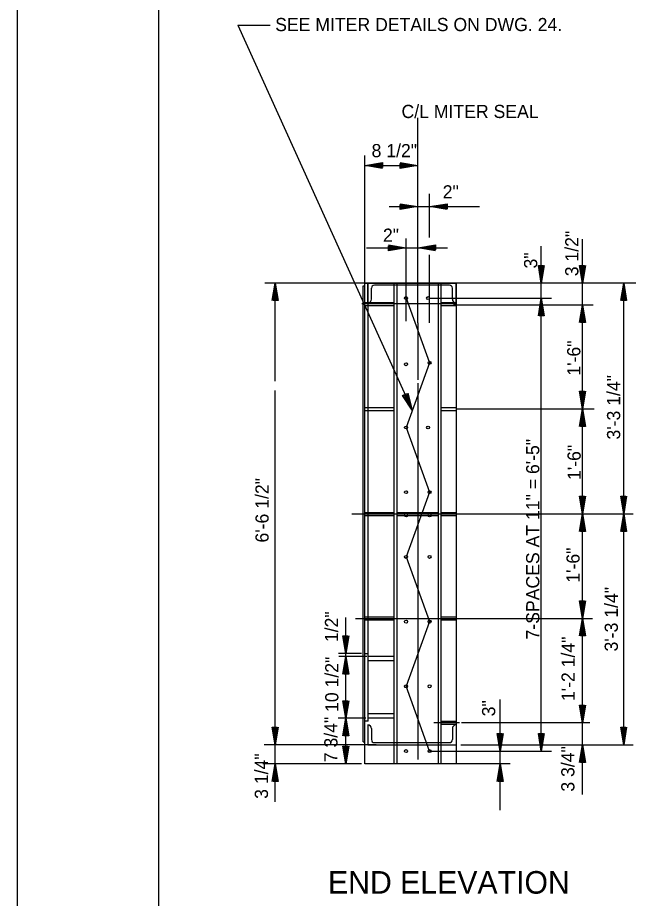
# Model space of a CAD drawing. Extents: x 0.6 to 54, y 0.6 to 38.
# Drawn here: x 0.63 to 9.53, y 12.03 to 24.51 of the extents above; entities that cross this region are included whole.
import ezdxf

# ---------------------------------------------------------------- set-up
doc = ezdxf.new("R2010")
doc.units = 0
for name, color, linetype in [('Level 1', 7, 'Continuous'), ('Level 2', 7, 'Continuous'), ('Level 25', 7, 'Continuous'), ('Level 50', 7, 'Continuous')]:
    doc.layers.add(name, color=color, linetype=linetype)

msp = doc.modelspace()

# ---------------------------------------------------------------- linework, layer by layer
at = {"layer": 'Level 1'}
for points in [[(0.625, 37.958), (53.958, 37.958), (53.958, 0.625), (0.625, 0.625)], [(2.625, 37.292), (53.292, 37.292), (53.292, 1.292), (2.625, 1.292)]]:
    msp.add_lwpolyline(points, close=True, dxfattribs=at)
at = {"layer": 'Level 25'}
for p, q in [((3.742, 24.398), (4.204, 24.398)), ((6.293, 20.185), (6.293, 23.087)), ((5.543, 20.747), (5.543, 22.555)), ((5.543, 22.412), (6.293, 22.412)), ((6.459, 21.394), (6.459, 22.008)), ((5.888, 21.829), (6.293, 21.829)), ((6.293, 21.829), (6.459, 21.829)), ((6.459, 21.829), (7.166, 21.829)), ((6.126, 20.206), (6.126, 21.379)), ((8.626, 20.747), (8.626, 21.366)), ((5.564, 21.245), (6.126, 21.245)), ((6.126, 21.245), (6.293, 21.245)), ((6.293, 21.245), (6.712, 21.245)), ((8.042, 20.747), (8.042, 21.271)), ((6.459, 20.185), (6.459, 21.147)), ((5.591, 20.747), (4.128, 20.747)), ((4.273, 19.355), (4.273, 20.747)), ((5.543, 20.747), (6.834, 20.747)), ((5.543, 19.247), (5.543, 20.747)), ((5.584, 20.466), (5.584, 20.747)), ((5.591, 19.247), (5.591, 20.747)), ((5.959, 19.247), (5.959, 20.747)), ((6.001, 19.247), (6.001, 20.747)), ((6.584, 19.247), (6.584, 20.747)), ((6.626, 19.247), (6.626, 20.747)), ((9.38, 20.747), (6.834, 20.747)), ((6.834, 20.747), (6.834, 19.247)), ((6.834, 20.466), (6.834, 20.747)), ((8.042, 20.534), (8.042, 20.747)), ((8.626, 20.435), (8.626, 20.747)), ((9.209, 17.477), (9.209, 20.747)), ((5.517, 20.706), (5.543, 20.706)), ((5.517, 19.247), (5.517, 20.706)), ((5.636, 20.518), (5.636, 20.675)), ((6.782, 20.518), (6.782, 20.675)), ((5.543, 20.471), (5.959, 20.471)), ((6.126, 20.534), (6.459, 19.617)), ((6.459, 20.534), (8.186, 20.534)), ((6.626, 20.471), (6.834, 20.471)), ((8.042, 14.117), (8.042, 20.534)), ((6.834, 20.451), (5.5, 20.451)), ((5.543, 20.43), (5.959, 20.43)), ((6.626, 20.43), (6.834, 20.43)), ((7.023, 20.435), (6.799, 20.435)), ((8.778, 20.435), (7.023, 20.435)), ((8.626, 18.964), (8.626, 20.435)), ((6.293, 20.185), (6.293, 19.374)), ((6.459, 19.617), (6.126, 18.7)), ((4.273, 13.935), (4.273, 19.225)), ((5.517, 14.248), (5.517, 19.247)), ((5.543, 14.248), (5.543, 19.247)), ((5.591, 15.497), (5.591, 19.247)), ((5.959, 13.935), (5.959, 19.247)), ((6.001, 13.935), (6.001, 19.247)), ((6.293, 19.326), (6.293, 13.996)), ((6.584, 13.935), (6.584, 19.247)), ((6.626, 13.935), (6.626, 19.247)), ((6.834, 19.247), (6.834, 13.935)), ((5.543, 18.984), (5.959, 18.984)), ((6.626, 18.984), (6.834, 18.984)), ((5.543, 18.943), (5.959, 18.943)), ((6.626, 18.943), (6.834, 18.943)), ((6.834, 18.964), (8.791, 18.964)), ((8.626, 17.477), (8.626, 18.964)), ((6.126, 18.7), (6.459, 17.784)), ((6.459, 17.784), (6.126, 16.867)), ((5.36, 17.477), (6.834, 17.477)), ((5.543, 17.497), (5.959, 17.497)), ((6.001, 17.497), (6.584, 17.497)), ((6.626, 17.497), (6.834, 17.497)), ((8.626, 15.997), (8.626, 17.477)), ((9.209, 14.206), (9.209, 17.477)), ((5.543, 17.456), (5.959, 17.456)), ((6.001, 17.456), (6.584, 17.456)), ((6.626, 17.456), (6.834, 17.456)), ((6.126, 16.867), (6.459, 15.95)), ((5.273, 15.497), (5.273, 16.01)), ((5.41, 15.997), (6.887, 15.997)), ((5.543, 16.018), (5.959, 16.018)), ((5.543, 15.977), (5.959, 15.977)), ((6.626, 16.018), (6.834, 16.018)), ((6.626, 15.977), (6.834, 15.977)), ((6.834, 15.997), (8.767, 15.997)), ((8.626, 14.518), (8.626, 15.997)), ((6.459, 15.95), (6.126, 15.034)), ((5.494, 15.497), (5.17, 15.497)), ((5.273, 15.417), (5.273, 15.528)), ((5.543, 15.497), (5.591, 15.497)), ((5.591, 14.539), (5.591, 15.497)), ((5.571, 15.456), (5.173, 15.456)), ((5.273, 14.581), (5.273, 15.456)), ((5.959, 15.456), (5.591, 15.456)), ((5.959, 15.393), (5.591, 15.393)), ((7.459, 14.117), (7.459, 14.848)), ((5.959, 14.643), (5.591, 14.643)), ((5.559, 14.581), (5.164, 14.581)), ((5.273, 13.935), (5.273, 14.581)), ((5.591, 14.539), (5.543, 14.539)), ((5.584, 14.487), (5.584, 14.206)), ((5.959, 14.581), (5.591, 14.581)), ((6.884, 14.518), (6.52, 14.518)), ((6.626, 14.539), (6.834, 14.539)), ((6.626, 14.497), (6.834, 14.497)), ((6.834, 14.487), (6.834, 14.206)), ((8.731, 14.518), (6.91, 14.518)), ((8.626, 14.206), (8.626, 14.518)), ((5.636, 14.435), (5.636, 14.279)), ((6.782, 14.435), (6.782, 14.279)), ((5.517, 14.248), (5.543, 14.248)), ((5.543, 13.935), (5.543, 14.248)), ((5.703, 14.206), (4.119, 14.206)), ((6.459, 14.117), (8.186, 14.117)), ((6.586, 14.206), (6.834, 14.206)), ((6.9, 14.206), (9.345, 14.206)), ((7.459, 13.935), (7.459, 14.117)), ((8.626, 13.5), (8.626, 14.206)), ((5.494, 13.935), (4.099, 13.935)), ((4.273, 13.399), (4.273, 13.935)), ((6.834, 13.935), (5.543, 13.935)), ((7.599, 13.935), (6.834, 13.935)), ((7.459, 13.279), (7.459, 13.935))]:
    msp.add_line(p, q, dxfattribs=at)
for centre in [(6.126, 20.534), (6.439, 20.534), (6.126, 19.596), (6.459, 19.617), (6.126, 18.7), (6.439, 18.7), (6.126, 17.784), (6.459, 17.784), (6.126, 17.456), (6.459, 17.456), (6.126, 16.867), (6.459, 16.867), (6.126, 15.95), (6.459, 15.95), (6.126, 15.034), (6.459, 15.034), (6.126, 14.117), (6.459, 14.117)]:
    msp.add_circle(centre, 0.0208, dxfattribs=at)
at = {"layer": 'Level 50'}
for p, q in [((3.742, 24.398), (6.215, 18.945)), ((5.543, 22.412), (5.543, 22.412)), ((5.612, 22.412), (5.612, 22.412)), ((6.223, 22.412), (6.223, 22.412)), ((6.293, 22.412), (6.293, 22.412)), ((6.223, 21.829), (6.223, 21.829)), ((6.293, 21.829), (6.293, 21.829)), ((6.459, 21.829), (6.459, 21.829)), ((6.529, 21.829), (6.529, 21.829)), ((6.057, 21.245), (6.057, 21.245)), ((6.057, 21.245), (6.057, 21.245)), ((6.126, 21.245), (6.126, 21.245)), ((6.126, 21.245), (6.126, 21.245)), ((6.293, 21.245), (6.293, 21.245)), ((6.362, 21.245), (6.362, 21.245)), ((4.273, 20.747), (4.273, 20.747)), ((6.834, 20.747), (5.584, 20.747)), ((6.741, 20.716), (5.678, 20.716)), ((8.042, 20.817), (8.042, 20.817)), ((8.042, 20.747), (8.042, 20.747)), ((8.626, 20.817), (8.626, 20.817)), ((8.626, 20.747), (8.626, 20.747)), ((9.209, 20.747), (9.209, 20.747)), ((4.273, 20.678), (4.273, 20.678)), ((9.209, 20.678), (9.209, 20.678)), ((8.042, 20.534), (8.042, 20.534)), ((8.042, 20.464), (8.042, 20.464)), ((8.626, 20.435), (8.626, 20.435)), ((8.626, 20.366), (8.626, 20.366)), ((6.186, 19.008), (6.186, 19.008)), ((8.626, 19.033), (8.626, 19.033)), ((6.215, 18.945), (6.215, 18.945)), ((8.626, 18.964), (8.626, 18.964)), ((8.626, 18.964), (8.626, 18.964)), ((8.626, 18.894), (8.626, 18.894)), ((6.834, 17.477), (9.344, 17.477)), ((8.626, 17.546), (8.626, 17.546)), ((8.626, 17.477), (8.626, 17.477)), ((8.626, 17.477), (8.626, 17.477)), ((9.209, 17.546), (9.209, 17.546)), ((9.209, 17.477), (9.209, 17.477)), ((9.209, 17.477), (9.209, 17.477)), ((8.626, 17.407), (8.626, 17.407)), ((9.209, 17.407), (9.209, 17.407)), ((8.626, 16.067), (8.626, 16.067)), ((8.626, 15.997), (8.626, 15.997)), ((8.626, 15.997), (8.626, 15.997)), ((8.626, 15.928), (8.626, 15.928)), ((5.273, 15.567), (5.273, 15.567)), ((5.273, 15.497), (5.273, 15.497)), ((5.273, 15.456), (5.273, 15.456)), ((5.273, 15.456), (5.273, 15.456)), ((5.273, 15.386), (5.273, 15.386)), ((5.273, 15.386), (5.273, 15.386)), ((6.459, 14.117), (6.126, 15.034)), ((5.273, 14.65), (5.273, 14.65)), ((5.273, 14.581), (5.273, 14.581)), ((5.273, 14.581), (5.273, 14.581)), ((5.273, 14.511), (5.273, 14.511)), ((8.626, 14.588), (8.626, 14.588)), ((8.626, 14.518), (8.626, 14.518)), ((4.273, 14.275), (4.273, 14.275)), ((5.678, 14.237), (6.741, 14.237)), ((9.209, 14.275), (9.209, 14.275)), ((4.273, 14.206), (4.273, 14.206)), ((5.584, 14.206), (6.834, 14.206)), ((7.459, 14.186), (7.459, 14.186)), ((7.459, 14.117), (7.459, 14.117)), ((8.042, 14.186), (8.042, 14.186)), ((8.042, 14.117), (8.042, 14.117)), ((8.626, 14.206), (8.626, 14.206)), ((8.626, 14.137), (8.626, 14.137)), ((9.209, 14.206), (9.209, 14.206)), ((5.273, 14.004), (5.273, 14.004)), ((4.273, 13.935), (4.273, 13.935)), ((4.273, 13.866), (4.273, 13.866)), ((5.273, 13.935), (5.273, 13.935)), ((7.459, 13.935), (7.459, 13.935)), ((7.459, 13.866), (7.459, 13.866))]:
    msp.add_line(p, q, dxfattribs=at)
for points in [[(5.792, 22.371), (5.543, 22.412), (5.792, 22.453), (5.792, 22.383), (5.612, 22.412), (5.782, 22.44), (5.782, 22.395), (5.679, 22.412), (5.771, 22.427), (5.771, 22.408), (5.748, 22.412)], [(6.043, 22.453), (6.293, 22.412), (6.043, 22.371), (6.043, 22.441), (6.223, 22.412), (6.054, 22.384), (6.054, 22.429), (6.157, 22.412), (6.065, 22.397), (6.065, 22.416), (6.087, 22.412)], [(6.043, 21.87), (6.293, 21.829), (6.043, 21.787), (6.043, 21.858), (6.223, 21.829), (6.054, 21.801), (6.054, 21.846), (6.157, 21.829), (6.065, 21.814), (6.065, 21.833), (6.087, 21.829)], [(6.709, 21.787), (6.459, 21.829), (6.709, 21.87), (6.709, 21.799), (6.529, 21.829), (6.698, 21.857), (6.698, 21.811), (6.595, 21.829), (6.687, 21.843), (6.687, 21.825), (6.665, 21.829)], [(5.877, 21.287), (6.126, 21.245), (5.877, 21.204), (5.877, 21.275), (6.057, 21.245), (5.887, 21.217), (5.887, 21.263), (5.99, 21.245), (5.898, 21.231), (5.898, 21.249), (5.921, 21.245)], [(5.877, 21.287), (6.126, 21.245), (5.877, 21.204), (5.877, 21.275), (6.057, 21.245), (5.887, 21.217), (5.887, 21.263), (5.99, 21.245), (5.898, 21.231), (5.898, 21.249), (5.921, 21.245)], [(6.542, 21.204), (6.293, 21.245), (6.542, 21.287), (6.542, 21.216), (6.362, 21.245), (6.531, 21.273), (6.531, 21.228), (6.429, 21.245), (6.521, 21.26), (6.521, 21.241), (6.498, 21.245)], [(8.084, 20.997), (8.042, 20.747), (8.001, 20.997), (8.072, 20.997), (8.042, 20.817), (8.014, 20.986), (8.06, 20.986), (8.042, 20.883), (8.028, 20.975), (8.046, 20.975), (8.042, 20.953)], [(8.667, 20.997), (8.626, 20.747), (8.584, 20.997), (8.655, 20.997), (8.626, 20.817), (8.598, 20.986), (8.643, 20.986), (8.626, 20.883), (8.611, 20.975), (8.63, 20.975), (8.626, 20.953)], [(4.232, 20.498), (4.273, 20.747), (4.315, 20.498), (4.244, 20.498), (4.273, 20.678), (4.301, 20.509), (4.256, 20.509), (4.273, 20.611), (4.288, 20.519), (4.269, 20.519), (4.273, 20.542)], [(9.168, 20.498), (9.209, 20.747), (9.25, 20.498), (9.18, 20.498), (9.209, 20.678), (9.237, 20.509), (9.192, 20.509), (9.209, 20.611), (9.224, 20.519), (9.205, 20.519), (9.209, 20.542)], [(8.001, 20.284), (8.042, 20.534), (8.084, 20.284), (8.013, 20.284), (8.042, 20.464), (8.07, 20.295), (8.025, 20.295), (8.042, 20.398), (8.057, 20.306), (8.038, 20.306), (8.042, 20.328)], [(8.584, 20.186), (8.626, 20.435), (8.667, 20.186), (8.596, 20.186), (8.626, 20.366), (8.654, 20.197), (8.608, 20.197), (8.626, 20.299), (8.64, 20.207), (8.622, 20.207), (8.626, 20.23)], [(6.15, 19.189), (6.215, 18.945), (6.074, 19.155), (6.139, 19.184), (6.186, 19.008), (6.091, 19.151), (6.132, 19.169), (6.159, 19.069), (6.107, 19.146), (6.124, 19.154), (6.13, 19.132)], [(8.667, 19.213), (8.626, 18.964), (8.584, 19.213), (8.655, 19.213), (8.626, 19.033), (8.598, 19.202), (8.643, 19.202), (8.626, 19.1), (8.611, 19.192), (8.63, 19.192), (8.626, 19.169)], [(8.584, 18.714), (8.626, 18.964), (8.667, 18.714), (8.596, 18.714), (8.626, 18.894), (8.654, 18.725), (8.608, 18.725), (8.626, 18.828), (8.64, 18.736), (8.622, 18.736), (8.626, 18.758)], [(8.667, 17.726), (8.626, 17.477), (8.584, 17.726), (8.655, 17.726), (8.626, 17.546), (8.598, 17.715), (8.643, 17.715), (8.626, 17.613), (8.611, 17.705), (8.63, 17.705), (8.626, 17.682)], [(9.25, 17.726), (9.209, 17.477), (9.168, 17.726), (9.238, 17.726), (9.209, 17.546), (9.181, 17.715), (9.226, 17.715), (9.209, 17.613), (9.194, 17.705), (9.213, 17.705), (9.209, 17.682)], [(8.584, 17.227), (8.626, 17.477), (8.667, 17.227), (8.596, 17.227), (8.626, 17.407), (8.654, 17.238), (8.608, 17.238), (8.626, 17.341), (8.64, 17.249), (8.622, 17.249), (8.626, 17.271)], [(9.168, 17.227), (9.209, 17.477), (9.25, 17.227), (9.18, 17.227), (9.209, 17.407), (9.237, 17.238), (9.192, 17.238), (9.209, 17.341), (9.224, 17.249), (9.205, 17.249), (9.209, 17.271)], [(8.667, 16.247), (8.626, 15.997), (8.584, 16.247), (8.655, 16.247), (8.626, 16.067), (8.598, 16.236), (8.643, 16.236), (8.626, 16.133), (8.611, 16.225), (8.63, 16.225), (8.626, 16.203)], [(8.584, 15.748), (8.626, 15.997), (8.667, 15.748), (8.596, 15.748), (8.626, 15.928), (8.654, 15.759), (8.608, 15.759), (8.626, 15.861), (8.64, 15.769), (8.622, 15.769), (8.626, 15.792)], [(5.315, 15.747), (5.273, 15.497), (5.232, 15.747), (5.303, 15.747), (5.273, 15.567), (5.245, 15.736), (5.291, 15.736), (5.273, 15.633), (5.259, 15.725), (5.277, 15.725), (5.273, 15.703)], [(5.232, 15.206), (5.273, 15.456), (5.315, 15.206), (5.244, 15.206), (5.273, 15.386), (5.301, 15.217), (5.256, 15.217), (5.273, 15.32), (5.288, 15.228), (5.269, 15.228), (5.273, 15.25)], [(5.232, 15.206), (5.273, 15.456), (5.315, 15.206), (5.244, 15.206), (5.273, 15.386), (5.301, 15.217), (5.256, 15.217), (5.273, 15.32), (5.288, 15.228), (5.269, 15.228), (5.273, 15.25)], [(5.315, 14.83), (5.273, 14.581), (5.232, 14.83), (5.303, 14.83), (5.273, 14.65), (5.245, 14.819), (5.291, 14.819), (5.273, 14.717), (5.259, 14.809), (5.277, 14.809), (5.273, 14.786)], [(8.667, 14.768), (8.626, 14.518), (8.584, 14.768), (8.655, 14.768), (8.626, 14.588), (8.598, 14.757), (8.643, 14.757), (8.626, 14.654), (8.611, 14.746), (8.63, 14.746), (8.626, 14.724)], [(5.232, 14.331), (5.273, 14.581), (5.315, 14.331), (5.244, 14.331), (5.273, 14.511), (5.301, 14.342), (5.256, 14.342), (5.273, 14.445), (5.288, 14.353), (5.269, 14.353), (5.273, 14.375)], [(4.315, 14.455), (4.273, 14.206), (4.232, 14.455), (4.303, 14.455), (4.273, 14.275), (4.245, 14.445), (4.291, 14.445), (4.273, 14.342), (4.259, 14.434), (4.277, 14.434), (4.273, 14.411)], [(7.5, 14.366), (7.459, 14.117), (7.418, 14.366), (7.488, 14.366), (7.459, 14.186), (7.431, 14.356), (7.476, 14.356), (7.459, 14.253), (7.444, 14.345), (7.463, 14.345), (7.459, 14.322)], [(8.084, 14.366), (8.042, 14.117), (8.001, 14.366), (8.072, 14.366), (8.042, 14.186), (8.014, 14.356), (8.06, 14.356), (8.042, 14.253), (8.028, 14.345), (8.046, 14.345), (8.042, 14.322)], [(9.25, 14.455), (9.209, 14.206), (9.168, 14.455), (9.238, 14.455), (9.209, 14.275), (9.181, 14.445), (9.226, 14.445), (9.209, 14.342), (9.194, 14.434), (9.213, 14.434), (9.209, 14.411)], [(5.315, 14.184), (5.273, 13.935), (5.232, 14.184), (5.303, 14.184), (5.273, 14.004), (5.245, 14.174), (5.291, 14.174), (5.273, 14.071), (5.259, 14.163), (5.277, 14.163), (5.273, 14.14)], [(8.584, 13.957), (8.626, 14.206), (8.667, 13.957), (8.596, 13.957), (8.626, 14.137), (8.654, 13.967), (8.608, 13.967), (8.626, 14.07), (8.64, 13.978), (8.622, 13.978), (8.626, 14.001)], [(4.232, 13.686), (4.273, 13.935), (4.315, 13.686), (4.244, 13.686), (4.273, 13.866), (4.301, 13.696), (4.256, 13.696), (4.273, 13.799), (4.288, 13.707), (4.269, 13.707), (4.273, 13.73)], [(7.418, 13.686), (7.459, 13.935), (7.5, 13.686), (7.43, 13.686), (7.459, 13.866), (7.487, 13.696), (7.442, 13.696), (7.459, 13.799), (7.474, 13.707), (7.455, 13.707), (7.459, 13.73)]]:
    msp.add_lwpolyline(points, dxfattribs=at)
for centre, radius, start, end in [((5.678, 20.675), 0.0417, 90, 180), ((6.741, 20.675), 0.0417, 0, 90), ((5.584, 20.518), 0.0521, 270, 0), ((6.834, 20.518), 0.0521, 180, 270), ((5.584, 14.435), 0.0521, 0, 90), ((6.834, 14.435), 0.0521, 90, 180), ((5.678, 14.279), 0.0417, 180, 270), ((6.741, 14.279), 0.0417, 270, 0)]:
    msp.add_arc(centre, radius, start, end, dxfattribs=at)

# ---------------------------------------------------------------- texts
at = {"layer": 'Level 2'}
msp.add_text('END ELEVATION', height=0.32, dxfattribs=at).set_placement((5.021, 12.097))
at = {"layer": 'Level 25'}
for s, height, p in [('SEE MITER DETAILS ON DWG. 24.', 0.18667, (4.273, 24.315)), ('C/L MITER SEAL', 0.18667, (6.062, 23.084)), ('8 1/2"', 0.1867, (5.638, 22.529)), ('2"', 0.1867, (6.646, 21.945)), ('2"', 0.1867, (5.799, 21.331))]:
    msp.add_text(s, height=height, dxfattribs=at).set_placement(p)
for s, height, p in [('3 1/2"', 0.1867, (8.567, 20.843)), ('3"', 0.1867, (7.984, 20.953)), ('1\'-6"', 0.1867, (8.595, 19.435)), ('3\'-3 1/4"', 0.1867, (9.159, 18.53)), ('7-SPACES AT 11" = 6\'-5"', 0.18667, (8.014, 15.698)), ('1\'-6"', 0.1867, (8.6, 17.957)), ('6\'-6 1/2"', 0.1867, (4.18, 17.071)), ('1\'-6"', 0.1867, (8.585, 16.502)), ('3\'-3 1/4"', 0.1867, (9.126, 15.528)), ('1/2"', 0.1867, (5.164, 15.66)), ('1\'-2 1/4"', 0.1867, (8.515, 14.825)), ('10 1/2"', 0.1867, (5.168, 14.671)), ('3"', 0.1867, (7.389, 14.609)), ('7 3/4"', 0.1867, (5.155, 13.959)), ('3 3/4"', 0.1867, (8.511, 13.542)), ('3 1/4"', 0.1867, (4.171, 13.44))]:
    msp.add_text(s, height=height, rotation=90, dxfattribs=at).set_placement(p)

doc.saveas('drawing.dxf')
